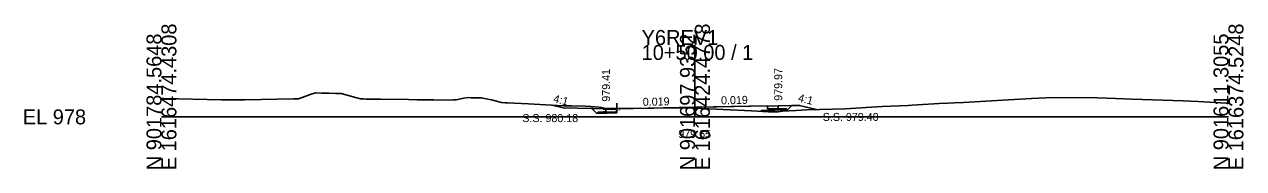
# Model space of a CAD drawing. Extents: x -26 to 203, y -10 to 2517.
# Drawn here: x -25.7 to 202.8, y 490.3 to 517.3 of the extents above; entities that cross this region are included whole.
import ezdxf

# ---------------------------------------------------------------- set-up
doc = ezdxf.new("R2010")
doc.units = 0
for name, color, linetype in [('Exist Cross Section Cell', 7, 'Continuous'), ('Exist XS Center Line Elevation Label', 7, 'Continuous'), ('Exist XS Ground Line', 7, 'Continuous'), ('Prop XS Dump Level', 7, 'Continuous'), ('Prop XS Earthwork Shape', 7, 'Continuous'), ('Prop XS EOT Tick Mark', 7, 'Continuous'), ('Prop XS Finish Grade', 7, 'Continuous'), ('Prop XS Finish Grade Earthwork', 7, 'Continuous'), ('Prop XS Finish Grade Pavement', 7, 'Continuous'), ('Prop XS Hydro Elevations', 7, 'Continuous'), ('Prop XS Pvmt Edge Slope', 7, 'Continuous'), ('Prop XS SE Text', 7, 'Continuous'), ('Prop XS Side Slope Text', 7, 'Continuous'), ('Prop XS SS Elevation Text', 7, 'Continuous'), ('Prop XS Subgrade CurbGutter', 7, 'Continuous'), ('Prop XS Subgrade Earthwork', 7, 'Continuous'), ('Scratch_Level_5', 7, 'Continuous')]:
    doc.layers.add(name, color=color, linetype=linetype)

msp = doc.modelspace()

# ---------------------------------------------------------------- linework, layer by layer
at = {"layer": 'Exist Cross Section Cell'}
for p, q in [((100, 500), (100, 513.47)), ((0, 500), (100, 500)), ((100, 500), (200, 500))]:
    msp.add_line(p, q, dxfattribs=at)
at = {"layer": 'Exist XS Ground Line'}
msp.add_lwpolyline([(0, 503.44), (0.42, 503.43), (11.26, 503.21), (15.65, 503.22), (24.77, 503.35), (25.7, 503.36), (28.05, 504.23), (28.87, 504.49), (30.06, 504.45), (31.37, 504.43), (32.68, 504.38), (33.41, 504.35), (33.71, 504.36), (36.36, 503.62), (37.3, 503.38), (37.84, 503.35), (38.33, 503.34), (41.03, 503.3), (46.32, 503.24), (47.94, 503.22), (49.93, 503.18), (51.03, 503.18), (52.41, 503.13), (54.77, 503.22), (55.24, 503.22), (56.69, 503.49), (57.6, 503.62), (58.08, 503.57), (58.93, 503.57), (59.93, 503.58), (61.15, 503.34), (61.85, 503.2), (63.73, 502.69), (64.43, 502.65), (64.81, 502.63), (68.79, 502.42), (74.2, 502.13), (75.39, 502.07), (75.8, 502.07), (76.83, 502.04), (79.4, 501.99), (80.48, 501.96), (81.99, 501.8), (82.5, 501.74), (83.18, 501.55), (84.97, 501.54), (99.6, 501.67), (100, 501.65), (110.59, 501.14), (113.81, 500.97), (114.73, 500.95), (115.62, 500.94), (115.96, 500.99), (116.4, 501.09), (118.95, 501.19), (120.95, 501.3), (128.14, 501.49), (135.06, 501.93), (139.97, 502.14), (140.72, 502.2), (141.74, 502.26), (145.79, 502.49), (147.39, 502.57), (148.6, 502.61), (150.33, 502.68), (156.67, 503.07), (163.08, 503.44), (165.74, 503.59), (169.38, 503.62), (175.43, 503.57), (177.23, 503.5), (180.43, 503.36), (181.94, 503.31), (191.49, 502.99), (194.31, 502.86), (199.59, 502.59), (200, 502.55)], dxfattribs=at)
at = {"layer": 'Prop XS Dump Level'}
msp.add_line((113.61, 502.06), (85.33, 501.49), dxfattribs=at)
at = {"layer": 'Prop XS Earthwork Shape'}
for points in [[(83.31, 501.49), (80.98, 501.54), (80.69, 501.55), (75.31, 501.66), (73.21, 502.19), (74.2, 502.13), (75.39, 502.07), (75.8, 502.07), (76.83, 502.04), (79.4, 501.99), (80.48, 501.96), (81.99, 501.8), (82.5, 501.74), (83.18, 501.55), (84.97, 501.54), (85.33, 501.54), (85.31, 501.49), (84.32, 501.41)], [(81.83, 500.91), (81.58, 500.65), (80.69, 501.55), (80.98, 501.54), (83.31, 501.49), (83.31, 500.94), (82.83, 500.93)], [(85.33, 500.73), (85.31, 500.91), (83.31, 500.94), (82.83, 500.93), (81.83, 500.91), (81.58, 500.65)], [(84.32, 501.41), (85.31, 501.49), (85.31, 500.91), (83.31, 500.94), (83.31, 501.49)], [(118.16, 502.11), (119.6, 502.14), (122.79, 501.35), (120.95, 501.3), (118.95, 501.19), (116.4, 501.09), (115.96, 500.99), (115.62, 500.94), (114.73, 500.95), (113.81, 500.97), (112.46, 501.04), (112.46, 501.21), (117.36, 501.3)]]:
    msp.add_lwpolyline(points, close=True, dxfattribs=at)
at = {"layer": 'Prop XS EOT Tick Mark'}
msp.add_line((85.33, 501.56), (85.33, 502.56), dxfattribs=at)
at = {"layer": 'Prop XS Finish Grade'}
for p, q in [((83.31, 501.49), (80.98, 501.54)), ((115.61, 502.06), (117.87, 502.11))]:
    msp.add_line(p, q, dxfattribs=at)
at = {"layer": 'Prop XS Finish Grade Earthwork'}
for p, q in [((73.21, 502.19), (75.31, 501.66)), ((83.31, 501.49), (75.31, 501.66)), ((115.61, 502.06), (119.6, 502.14)), ((119.6, 502.14), (122.79, 501.35))]:
    msp.add_line(p, q, dxfattribs=at)
at = {"layer": 'Prop XS Finish Grade Pavement'}
for p, q in [((85.33, 501.49), (100, 501.79)), ((100, 501.79), (113.61, 502.06))]:
    msp.add_line(p, q, dxfattribs=at)
at = {"layer": 'Prop XS Pvmt Edge Slope'}
for p, q in [((81.83, 500.91), (81.58, 500.65)), ((82.83, 500.93), (81.83, 500.91)), ((116.11, 501.53), (117.11, 501.55)), ((117.11, 501.55), (117.36, 501.3))]:
    msp.add_line(p, q, dxfattribs=at)
at = {"layer": 'Prop XS Subgrade CurbGutter'}
for p, q in [((83.31, 500.94), (82.83, 500.93)), ((83.31, 500.91), (83.31, 501.49)), ((83.31, 501.49), (84.32, 501.41)), ((85.31, 500.91), (83.31, 500.91)), ((84.32, 501.41), (85.31, 501.49)), ((113.61, 502.06), (113.61, 501.48)), ((113.61, 501.48), (113.61, 502.06)), ((113.61, 502.06), (114.62, 501.98)), ((115.61, 501.48), (113.61, 501.48)), ((114.62, 501.98), (115.61, 502.06)), ((115.61, 501.52), (116.11, 501.53))]:
    msp.add_line(p, q, dxfattribs=at)
for points in [[(83.31, 500.91), (85.31, 500.91), (85.31, 501.49)], [(113.61, 501.48), (115.61, 501.48), (115.61, 502.06)]]:
    msp.add_lwpolyline(points, dxfattribs=at)
at = {"layer": 'Prop XS Subgrade Earthwork'}
for p, q in [((81.58, 500.65), (80.69, 501.55)), ((85.33, 500.73), (81.58, 500.65)), ((85.33, 500.73), (85.33, 501.54)), ((112.46, 501.21), (117.36, 501.3)), ((112.46, 501.21), (112.46, 501.04)), ((117.36, 501.3), (118.16, 502.11))]:
    msp.add_line(p, q, dxfattribs=at)
at = {"layer": 'Scratch_Level_5'}
msp.add_line((85.33, 501.45), (82.81, 501.45), dxfattribs=at)

# ---------------------------------------------------------------- texts
at = {"layer": 'Exist Cross Section Cell'}
for s, p in [('E 1616474.4308', (2.8, 490)), ('E 1616424.4778', (102.8, 490)), ('E 1616374.5248', (202.8, 490)), ('N 901784.5648', (0, 490)), ('N 901697.9352', (100, 490)), ('N 901611.3055', (200, 490))]:
    msp.add_text(s, height=2.8, rotation=90, dxfattribs=at).set_placement(p)
for s, p in [('Y6REV1', (90, 513.47)), ('10+50.00 / 1', (90, 510.67)), ('EL 978', (-26, 498.6))]:
    msp.add_text(s, height=2.8, dxfattribs=at).set_placement(p)
at = {"layer": 'Exist XS Center Line Elevation Label'}
msp.add_text('979.65', height=1.5, dxfattribs=at).set_placement((96.88, 496.05))
msp.add_text('979.65', height=1.5, dxfattribs=at).set_placement((96.88, 496.05))
at = {"layer": 'Prop XS Dump Level'}
msp.add_text('Eop', height=0.3, dxfattribs=at).set_placement((85.31, 501.19))
at = {"layer": 'Prop XS Hydro Elevations'}
for s, p in [('979.41', (84.08, 502.84)), ('979.97', (116.36, 503.01))]:
    msp.add_text(s, height=1.5, rotation=90, dxfattribs=at).set_placement(p)
at = {"layer": 'Prop XS SE Text'}
for p in [(90.23, 502.06), (104.9, 502.34)]:
    msp.add_text('0.019', height=1.5, rotation=1.1458, dxfattribs=at).set_placement(p)
at = {"layer": 'Prop XS Side Slope Text'}
for p in [(73.35, 502.78), (119.23, 502.92)]:
    msp.add_text('4:1', height=1.5, rotation=345.9638, dxfattribs=at).set_placement(p)
at = {"layer": 'Prop XS SS Elevation Text'}
for s, p in [('S.S. 980.18', (67.63, 499.02)), ('S.S. 979.40', (123.95, 499.24))]:
    msp.add_text(s, height=1.5, dxfattribs=at).set_placement(p)

doc.saveas('drawing.dxf')
